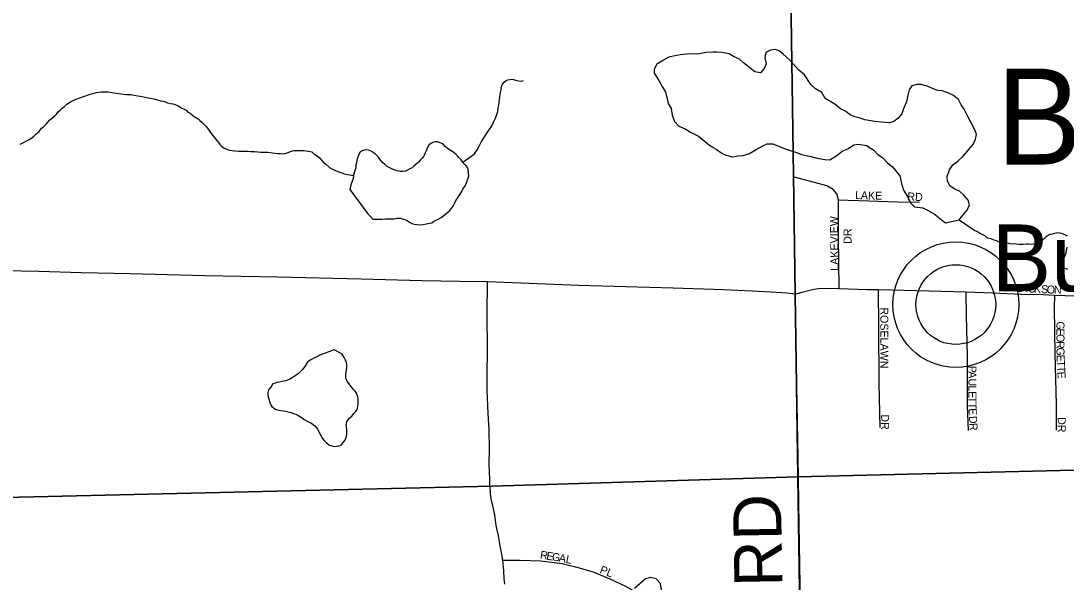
# Model space of a CAD drawing. Extents: x 0 to 34, y 0 to 22.
# Drawn here: x 3.494 to 4.731, y 19.552 to 20.216 of the extents above; entities that cross this region are included whole.
import ezdxf

# ---------------------------------------------------------------- set-up
doc = ezdxf.new("R2010")
doc.units = 0
for name, color, linetype in [('GM_X_Minor_Lake', 7, 'Continuous'), ('GM_X_Minor_Lake_Text', 7, 'Continuous'), ('GM_X_Minor_River', 7, 'Continuous'), ('GM_X_Township', 7, 'Continuous'), ('GM_X_Township_Road', 7, 'Continuous'), ('GM_X_Township_Road_Text', 7, 'Continuous'), ('GM_X_Township_Subdivision', 7, 'Continuous'), ('GM_X_Township_Subdivision_Text', 7, 'Continuous'), ('GM_X_Unincorporated', 7, 'Continuous'), ('GM_X_Unincorporated_Text', 7, 'Continuous')]:
    doc.layers.add(name, color=color, linetype=linetype)

msp = doc.modelspace()

# ---------------------------------------------------------------- linework, layer by layer
at = {"layer": 'GM_X_Minor_Lake'}
for points in [[(4.5273, 20.0973), (4.522, 20.0957), (4.5167, 20.0961), (4.5046, 20.0972), (4.4928, 20.0991), (4.4875, 20.101), (4.481, 20.1029), (4.4753, 20.1052), (4.4693, 20.1097), (4.464, 20.112), (4.4575, 20.1177), (4.4461, 20.1245), (4.442, 20.1317), (4.4344, 20.1359), (4.4291, 20.1408), (4.4215, 20.1526), (4.4143, 20.1583), (4.404, 20.1697), (4.3964, 20.1769), (4.3915, 20.1807), (4.3866, 20.1826), (4.3813, 20.1818), (4.3756, 20.1788), (4.3744, 20.1731), (4.3759, 20.1655), (4.3737, 20.1601), (4.3695, 20.1548), (4.3627, 20.156), (4.3494, 20.1666), (4.3445, 20.1711), (4.3376, 20.1742), (4.3323, 20.1772), (4.3236, 20.1787), (4.3179, 20.1794), (4.313, 20.1794), (4.305, 20.1787), (4.2951, 20.1768), (4.2845, 20.1771), (4.2746, 20.176), (4.2659, 20.1745), (4.261, 20.1733), (4.2545, 20.1699), (4.2466, 20.1649), (4.2435, 20.1592), (4.2435, 20.1543), (4.2485, 20.1467), (4.2534, 20.138), (4.2568, 20.1319), (4.2587, 20.1258), (4.2602, 20.1186), (4.2636, 20.1125), (4.2648, 20.1046), (4.2678, 20.097), (4.2727, 20.0917), (4.2796, 20.089), (4.2875, 20.0841), (4.2959, 20.0799), (4.3046, 20.0727), (4.3107, 20.0678), (4.3171, 20.0644), (4.3236, 20.0598), (4.3289, 20.0575), (4.3361, 20.0553), (4.3429, 20.0564), (4.349, 20.0568), (4.3562, 20.0591), (4.3642, 20.064), (4.3721, 20.0682), (4.3771, 20.0709), (4.3839, 20.0709), (4.3907, 20.0679), (4.3998, 20.0645), (4.4131, 20.0599), (4.418, 20.058), (4.4275, 20.0561), (4.4366, 20.0539), (4.4454, 20.052), (4.4514, 20.0516), (4.4598, 20.0569), (4.4662, 20.0619), (4.4734, 20.0653), (4.4799, 20.0695), (4.4848, 20.0703), (4.4947, 20.0687), (4.5034, 20.0631), (4.5083, 20.0581), (4.5137, 20.0547), (4.5193, 20.0486), (4.5254, 20.0437), (4.5341, 20.0327), (4.5364, 20.0236), (4.5387, 20.016), (4.5432, 20.0084), (4.5467, 20.0008), (4.5516, 19.9963), (4.5615, 19.9948), (4.5671, 19.9921), (4.5759, 19.9872), (4.5816, 19.9822), (4.5884, 19.9773), (4.6043, 19.9808)], [(4.6043, 19.9808), (4.6093, 19.9868), (4.6138, 19.9922), (4.6168, 19.9986), (4.615, 20.0039), (4.61, 20.01), (4.6047, 20.0146), (4.5994, 20.0172), (4.5937, 20.0206), (4.5907, 20.0267), (4.5903, 20.032), (4.593, 20.04), (4.5971, 20.0457), (4.6028, 20.0503), (4.6085, 20.0552), (4.6138, 20.0617), (4.6214, 20.0708), (4.6237, 20.0761), (4.6248, 20.0818), (4.6233, 20.0867), (4.6191, 20.0947), (4.6142, 20.1038), (4.6104, 20.1118), (4.607, 20.1171), (4.6036, 20.1232), (4.5979, 20.1281), (4.5911, 20.1312), (4.5842, 20.1334), (4.5793, 20.1338), (4.5729, 20.1361), (4.5668, 20.1391), (4.56, 20.141), (4.5543, 20.141), (4.5486, 20.1395), (4.5452, 20.1345), (4.5436, 20.1284), (4.5421, 20.1205), (4.5391, 20.1132), (4.5368, 20.1064), (4.5323, 20.1011), (4.5273, 20.0973)], [(3.9596, 19.9755), (3.963, 19.9752), (3.9664, 19.9749), (3.9702, 19.9754), (3.9736, 19.9759), (3.9763, 19.9763), (3.9782, 19.9767), (3.9804, 19.9771), (3.9823, 19.9787), (3.9849, 19.9799), (3.988, 19.9815), (3.9913, 19.9835), (3.9947, 19.9858), (3.997, 19.9878), (3.9999, 19.9901), (4.0018, 19.992), (4.0037, 19.9947), (4.0055, 19.9971), (4.0077, 20.0009), (4.0088, 20.0036), (4.0103, 20.0055), (4.0121, 20.0082), (4.0139, 20.0113), (4.0158, 20.0144), (4.0172, 20.0171), (4.0191, 20.0198), (4.0206, 20.0225), (4.022, 20.0255), (4.0227, 20.0282), (4.0234, 20.0301), (4.0241, 20.0328), (4.0236, 20.04), (4.0228, 20.0427), (4.0208, 20.0449), (4.0193, 20.0468), (4.0173, 20.049), (4.015, 20.0516), (4.0123, 20.0546), (4.0107, 20.0565), (4.0091, 20.0583), (4.0072, 20.0598), (4.0053, 20.0613), (4.0022, 20.0631), (3.9991, 20.0653), (3.9964, 20.0675), (3.9941, 20.0698), (3.9921, 20.0713), (3.9902, 20.072), (3.9871, 20.073), (3.9849, 20.073), (3.9818, 20.0725), (3.9792, 20.071), (3.977, 20.069), (3.9755, 20.0663), (3.9744, 20.0644), (3.9737, 20.0625), (3.9726, 20.0602), (3.9715, 20.0575), (3.9704, 20.0556), (3.9689, 20.0537), (3.9667, 20.0513), (3.9641, 20.0486), (3.9615, 20.0463), (3.9592, 20.0443), (3.957, 20.0424), (3.9543, 20.0412), (3.9517, 20.0396), (3.9491, 20.0384), (3.946, 20.038), (3.943, 20.0379), (3.9396, 20.0386), (3.9365, 20.0396), (3.9338, 20.0407), (3.9269, 20.0444), (3.9249, 20.0462), (3.9222, 20.0488), (3.9203, 20.0507), (3.9187, 20.0529), (3.9172, 20.0548), (3.9156, 20.0567), (3.9137, 20.0585), (3.9113, 20.06), (3.9094, 20.0615), (3.9075, 20.0626), (3.9056, 20.0633), (3.9033, 20.0636), (3.9002, 20.0632), (3.898, 20.0624), (3.8957, 20.0608), (3.8939, 20.0581), (3.8921, 20.0531), (3.8917, 20.0512), (3.8914, 20.0482), (3.8907, 20.0455), (3.8904, 20.0424), (3.889, 20.0375), (3.8879, 20.0333), (3.8873, 20.0298), (3.8862, 20.0264), (3.8844, 20.0222), (3.8834, 20.0165)], [(3.8834, 20.0165), (3.9049, 19.9877), (3.9068, 19.9858), (3.9107, 19.9817), (3.9126, 19.9814), (3.9172, 19.9815), (3.9218, 19.9816), (3.9256, 19.982), (3.9294, 19.9821), (3.9332, 19.9818), (3.9358, 19.9819), (3.9392, 19.9827), (3.9411, 19.9827), (3.943, 19.9828), (3.9465, 19.9817), (3.9492, 19.9806), (3.9515, 19.9796), (3.9542, 19.9781), (3.9569, 19.9766), (3.9596, 19.9755)], [(3.865, 19.8268), (3.848, 19.8204), (3.8442, 19.8184), (3.8408, 19.8168), (3.8382, 19.8156), (3.8363, 19.8148), (3.8333, 19.8121), (3.8322, 19.8101), (3.83, 19.8071), (3.8271, 19.8032), (3.8226, 19.7989), (3.8185, 19.7958), (3.8132, 19.7926), (3.8098, 19.791), (3.8072, 19.7902), (3.8053, 19.7898), (3.8034, 19.7894), (3.7996, 19.7885), (3.7969, 19.7881), (3.7951, 19.7873), (3.7924, 19.7865), (3.7895, 19.7822), (3.7872, 19.7795), (3.7862, 19.7765), (3.7862, 19.7727), (3.7883, 19.7659), (3.7887, 19.764), (3.7899, 19.7617), (3.7911, 19.7598), (3.793, 19.758), (3.7953, 19.7565), (3.798, 19.7558), (3.8018, 19.7551), (3.8053, 19.7548), (3.8087, 19.7538), (3.8137, 19.7527), (3.8168, 19.7513), (3.8194, 19.7506), (3.8217, 19.7495), (3.8252, 19.7477), (3.8271, 19.7462), (3.8295, 19.7443), (3.8321, 19.7429), (3.8345, 19.7418), (3.8364, 19.7407), (3.8383, 19.7396), (3.8418, 19.737), (3.8437, 19.7348), (3.8457, 19.7325), (3.8473, 19.7288), (3.8489, 19.7254), (3.8508, 19.7224), (3.8532, 19.7194), (3.8559, 19.7168), (3.8594, 19.7138), (3.8636, 19.7128), (3.8655, 19.7124), (3.8678, 19.7129), (3.8704, 19.7133), (3.8731, 19.7141), (3.8775, 19.7195), (3.8786, 19.7222), (3.8793, 19.7241), (3.8797, 19.7272), (3.88, 19.7295), (3.8799, 19.7321), (3.8795, 19.7355), (3.879, 19.7378), (3.8797, 19.7416), (3.8816, 19.744), (3.8827, 19.7459), (3.8857, 19.7482), (3.8883, 19.7513), (3.8901, 19.7533), (3.8916, 19.7556), (3.8923, 19.7579), (3.893, 19.7602), (3.8934, 19.7625), (3.8932, 19.7682), (3.8928, 19.7712), (3.8912, 19.7757), (3.8896, 19.778), (3.8877, 19.7798), (3.8861, 19.7817), (3.8822, 19.7869), (3.8802, 19.7899), (3.879, 19.7925), (3.8786, 19.7948), (3.8785, 19.7975), (3.8789, 19.8005), (3.8796, 19.8032), (3.8799, 19.8055), (3.8798, 19.8074), (3.8798, 19.8093), (3.8794, 19.8119), (3.8782, 19.8146), (3.8766, 19.8179), (3.8742, 19.8217)], [(3.8742, 19.8217), (3.8665, 19.8261), (3.8657, 19.8265), (3.865, 19.8268)]]:
    msp.add_lwpolyline(points, dxfattribs=at)
at = {"layer": 'GM_X_Minor_River'}
for points in [[(4.0173, 20.049), (4.0308, 20.0588), (4.0341, 20.0638), (4.0367, 20.0688), (4.0392, 20.0734), (4.0415, 20.0769), (4.0437, 20.0804), (4.0462, 20.0846), (4.0492, 20.0885), (4.0514, 20.0919), (4.0536, 20.0962), (4.0554, 20.1004), (4.0572, 20.1054), (4.0586, 20.1092), (4.0589, 20.1134), (4.0596, 20.1164), (4.0603, 20.1187), (4.0603, 20.121), (4.0606, 20.1233), (4.0609, 20.126), (4.0613, 20.129), (4.0616, 20.1317), (4.0623, 20.1347), (4.0626, 20.137), (4.0633, 20.1393), (4.064, 20.1412), (4.0659, 20.1439), (4.0685, 20.1459), (4.0704, 20.1467), (4.0727, 20.1471), (4.0753, 20.1472), (4.0772, 20.1468), (4.0795, 20.1461), (4.083, 20.1454), (4.0853, 20.1451), (4.0883, 20.1455), (4.0887, 20.1456), (4.0883, 20.1455)], [(3.4934, 20.0703), (3.4987, 20.0731), (3.5032, 20.0754), (3.507, 20.0778), (3.5096, 20.0798), (3.5118, 20.0821), (3.5156, 20.0852), (3.5185, 20.0891), (3.5208, 20.091), (3.5241, 20.0941), (3.526, 20.0965), (3.5286, 20.0992), (3.5319, 20.1019), (3.5342, 20.1039), (3.5364, 20.1058), (3.5383, 20.1085), (3.5409, 20.1108), (3.5431, 20.1128), (3.5457, 20.1151), (3.5487, 20.1178), (3.5528, 20.1206), (3.5577, 20.123), (3.5683, 20.1266), (3.571, 20.1274), (3.5751, 20.1291), (3.5778, 20.1299), (3.5808, 20.1307), (3.5838, 20.1315), (3.5861, 20.132), (3.5887, 20.1324), (3.5914, 20.1325), (3.5941, 20.1325), (3.5975, 20.1322), (3.6017, 20.1315), (3.607, 20.1309), (3.6124, 20.1299), (3.6192, 20.1293), (3.6242, 20.129), (3.6303, 20.128), (3.6375, 20.1266), (3.6448, 20.1253), (3.6513, 20.1239), (3.6559, 20.1228), (3.6593, 20.1218), (3.6624, 20.1211), (3.6651, 20.1204), (3.6678, 20.1193), (3.6712, 20.1186), (3.6739, 20.1179), (3.6769, 20.1172), (3.6804, 20.1158), (3.6846, 20.1128), (3.6873, 20.1117), (3.6896, 20.1107), (3.6912, 20.1088), (3.6946, 20.107), (3.6974, 20.1047), (3.6997, 20.1029), (3.702, 20.1014), (3.7039, 20.1003), (3.7059, 20.0985), (3.7082, 20.0962), (3.7105, 20.094), (3.7129, 20.0918), (3.7148, 20.0892), (3.7168, 20.0865), (3.7195, 20.0828), (3.7262, 20.0746), (3.7281, 20.0724), (3.7301, 20.0697), (3.7316, 20.0679), (3.7347, 20.0657), (3.7374, 20.0646), (3.7409, 20.0631), (3.7473, 20.0625), (3.7519, 20.0622), (3.7553, 20.0619), (3.7588, 20.062), (3.7622, 20.0621), (3.766, 20.0618), (3.7702, 20.0615), (3.7747, 20.0612), (3.7782, 20.0609), (3.782, 20.061), (3.7862, 20.0607), (3.7915, 20.06), (3.7949, 20.0597), (3.7984, 20.0594), (3.8014, 20.0591), (3.8052, 20.0588), (3.8079, 20.0596), (3.8105, 20.0605), (3.8132, 20.0617), (3.8154, 20.0625)], [(3.8154, 20.0625), (3.8177, 20.0629), (3.823, 20.063), (3.8284, 20.0628), (3.8314, 20.0624), (3.8345, 20.0621), (3.8364, 20.0618), (3.8383, 20.0611), (3.8402, 20.0596), (3.8425, 20.0581), (3.8452, 20.0563), (3.8476, 20.054), (3.8503, 20.0511), (3.8522, 20.0488), (3.8546, 20.047), (3.8592, 20.0429), (3.8638, 20.0403), (3.8711, 20.0371), (3.8742, 20.0364), (3.8769, 20.0353), (3.8879, 20.0333)], [(4.6043, 19.9808), (4.6231, 19.9683), (4.6262, 19.9669), (4.6297, 19.9647), (4.632, 19.9632), (4.6351, 19.9618), (4.6378, 19.9595), (4.642, 19.9585), (4.6454, 19.957), (4.6481, 19.9563), (4.6508, 19.9553), (4.6539, 19.9546), (4.6573, 19.9539), (4.6603, 19.9536), (4.663, 19.9532), (4.6657, 19.9525), (4.6684, 19.9526), (4.6718, 19.9523), (4.6756, 19.952), (4.6783, 19.9521), (4.6802, 19.9521), (4.6836, 19.9522), (4.6866, 19.9522), (4.6897, 19.9519), (4.6923, 19.9524), (4.6954, 19.9528), (4.6984, 19.954), (4.7006, 19.9548), (4.7029, 19.9568), (4.7074, 19.961), (4.7096, 19.9626), (4.7122, 19.9638), (4.7149, 19.9643), (4.7172, 19.9651), (4.7191, 19.9655), (4.7209, 19.9659), (4.7255, 19.9649), (4.7282, 19.9638), (4.7301, 19.9631), (4.7324, 19.962)], [(4.732, 19.9483), (4.7309, 19.9441), (4.7302, 19.9403), (4.7288, 19.9361), (4.7274, 19.9315), (4.7259, 19.9288), (4.7264, 19.9265), (4.7275, 19.9246), (4.7295, 19.9235), (4.7325, 19.9225)]]:
    msp.add_lwpolyline(points, dxfattribs=at)
at = {"layer": 'GM_X_Township'}
for points in [[(2.3622, 19.6335), (3.407, 19.6503), (4.0516, 19.6654), (4.4134, 19.6764), (4.4103, 19.8926), (4.4083, 20.0336), (4.3978, 20.7562), (4.3964, 21.0758), (4.3953, 21.1385)], [(4.3953, 21.1385), (4.3964, 21.0758), (4.3978, 20.7562), (4.4083, 20.0336), (4.4103, 19.8926), (4.4134, 19.6764), (5.8028, 19.7101), (6.782, 19.7315), (7.8005, 19.7395), (8.817, 19.7645), (9.1622, 19.7691)], [(9.1622, 19.7691), (8.817, 19.7645), (7.8005, 19.7395), (6.782, 19.7315), (5.8028, 19.7101), (4.4134, 19.6764), (4.4176, 19.4076), (4.4274, 18.8628), (4.4298, 18.3764)], [(4.4298, 18.3764), (4.4274, 18.8628), (4.4176, 19.4076), (4.4134, 19.6764), (4.0516, 19.6654), (3.407, 19.6503), (2.3622, 19.6335)]]:
    msp.add_lwpolyline(points, dxfattribs=at)
at = {"layer": 'GM_X_Township_Road'}
for points in [[(4.4103, 19.8926), (4.4007, 19.8939), (4.3818, 19.895), (4.3595, 19.8963), (4.3256, 19.8977), (4.266, 19.8998), (4.21, 19.9014), (4.1546, 19.903), (4.0463, 19.9074), (4.0137, 19.9079), (3.9685, 19.9087), (3.8968, 19.9104), (3.7978, 19.913), (3.7117, 19.9143), (3.6233, 19.9168), (3.5655, 19.9181), (3.5152, 19.9197), (3.4547, 19.9208), (3.4375, 19.9216)], [(4.0498, 19.6566), (4.0498, 19.6573), (4.0493, 19.6654), (4.0492, 19.6672), (4.0489, 19.6739), (4.0484, 19.6917), (4.0487, 19.7089), (4.0484, 19.7326), (4.0473, 19.7511), (4.046, 19.7794), (4.046, 19.7987), (4.0465, 19.8251), (4.046, 19.8697), (4.0463, 19.9074)], [(4.4149, 19.6447), (4.4144, 19.6764), (4.4124, 19.7845), (4.4103, 19.8926)], [(4.0667, 19.5494), (4.0662, 19.5562), (4.0656, 19.5653), (4.0645, 19.5777), (4.0632, 19.5847), (4.0613, 19.5949), (4.0592, 19.6065), (4.0567, 19.6188), (4.0549, 19.6317), (4.0527, 19.6422), (4.0506, 19.6503), (4.0498, 19.6566)], [(4.4288, 18.8614), (4.4191, 19.3797), (4.4149, 19.6447)]]:
    msp.add_lwpolyline(points, dxfattribs=at)
at = {"layer": 'GM_X_Township_Subdivision'}
for points in [[(4.4625, 19.8993), (4.4618, 19.9613), (4.4618, 19.9899), (4.4617, 20.0044), (4.4596, 20.0114), (4.4555, 20.0165), (4.4477, 20.0211), (4.4332, 20.0249), (4.4082, 20.0316)], [(4.4617, 20.0044), (4.473, 20.0039), (4.4975, 20.0033), (4.5314, 20.002), (4.5577, 20.0017)], [(4.4103, 19.8926), (4.4203, 19.8955), (4.4324, 19.8985), (4.4413, 19.8998), (4.4625, 19.8993), (4.4951, 19.8982), (4.5088, 19.8982), (4.5246, 19.8977), (4.6123, 19.8955), (4.6443, 19.8944), (4.6779, 19.8928), (4.7037, 19.8923), (4.7174, 19.8915), (4.7683, 19.8899)], [(4.5088, 19.8982), (4.5091, 19.8538), (4.5095, 19.7874), (4.5107, 19.735)], [(4.6123, 19.8955), (4.6128, 19.8676), (4.6139, 19.8194), (4.6139, 19.7605), (4.6153, 19.7315)], [(4.7174, 19.8915), (4.7169, 19.8764), (4.7177, 19.8216), (4.7191, 19.7627), (4.7193, 19.7318)], [(4.0645, 19.5777), (4.085, 19.5779), (4.1092, 19.5771), (4.1345, 19.5739), (4.1503, 19.5699), (4.1713, 19.564), (4.1912, 19.5556), (4.2095, 19.547), (4.2245, 19.5387), (4.2331, 19.5338), (4.2393, 19.5322), (4.2461, 19.5341), (4.2504, 19.5376), (4.2522, 19.5427), (4.2512, 19.5503), (4.2461, 19.5556), (4.2391, 19.5575), (4.2334, 19.5556), (4.2202, 19.5441)]]:
    msp.add_lwpolyline(points, dxfattribs=at)
at = {"layer": 'GM_X_Unincorporated'}
for radius in [0.0744, 0.0472]:
    msp.add_circle((4.6005, 19.8804), radius, dxfattribs=at)

# ---------------------------------------------------------------- texts
at = {"layer": 'GM_X_Minor_Lake_Text'}
msp.add_text('Burton', height=0.1137, rotation=0.067, dxfattribs=at).set_placement((4.6482, 20.0461))
at = {"layer": 'GM_X_Township_Road_Text'}
msp.add_text('RD', height=0.05682, rotation=90.9872, dxfattribs=at).set_placement((4.3954, 19.5468))
at = {"layer": 'GM_X_Township_Subdivision_Text'}
for s, rotation, p in [('L', 357.3763, (4.4812, 20.0055)), ('A', 357.3766, (4.4879, 20.0052)), ('K', 359.1595, (4.4965, 20.0048)), ('E', 359.9073, (4.505, 20.0047)), ('RD', 356.8215, (4.5429, 20.0039)), ('LAKEVIEW', 90.7844, (4.4618, 19.9205)), ('DR', 90, (4.4771, 19.9522)), ('J', 356.8517, (4.6729, 19.8956)), ('A', 356.8287, (4.677, 19.8954)), ('C', 356.8439, (4.6854, 19.8949)), ('K', 356.8287, (4.6928, 19.8945)), ('S', 356.8605, (4.7012, 19.8941)), ('O', 357.0656, (4.7079, 19.8937)), ('N', 359.2159, (4.7166, 19.8933)), ('ROSELAWN', 270, (4.5112, 19.8772)), ('G', 270.0219, (4.7196, 19.8605)), ('O', 270.0154, (4.7196, 19.8455)), ('E', 270.0206, (4.7196, 19.8522)), ('G', 270.522, (4.7196, 19.8296)), ('R', 270, (4.7196, 19.8372)), ('E', 272.6035, (4.7197, 19.8209)), ('T', 273.1668, (4.72, 19.8141)), ('P', 270.0273, (4.6154, 19.808)), ('T', 273.1797, (4.7203, 19.8075)), ('U', 270.0154, (4.6154, 19.793)), ('A', 270, (4.6154, 19.8014)), ('E', 273.1919, (4.7207, 19.8008)), ('L', 270.0206, (4.6154, 19.7847)), ('E', 270, (4.6154, 19.778)), ('T', 270.0206, (4.6154, 19.7714)), ('T', 271.4259, (4.6154, 19.7644)), ('E', 273.0167, (4.6156, 19.7575)), ('DR', 270, (4.5121, 19.7505)), ('D', 273.1713, (4.6161, 19.7483)), ('DR', 270, (4.7212, 19.7472)), ('R', 273.1583, (4.6165, 19.74)), ('R', 351.0766, (4.108, 19.5798)), ('E', 351.0896, (4.1155, 19.5786)), ('G', 351.091, (4.122, 19.5776)), ('A', 349.6717, (4.1302, 19.5763)), ('L', 348.0312, (4.1383, 19.5748)), ('PL', 338.1961, (4.1784, 19.563))]:
    msp.add_text(s, height=0.00947, rotation=rotation, dxfattribs=at).set_placement(p)
at = {"layer": 'GM_X_Unincorporated_Text'}
msp.add_text('Burton Lake', height=0.078977, rotation=0, dxfattribs=at).set_placement((4.6428, 19.8963))

doc.saveas('drawing.dxf')
